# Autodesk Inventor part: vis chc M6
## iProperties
Library Location: C:\Program Files\Autodesk\Inventor 6\content
Library: local
SubLibrary: ISO
Family: 13
Member: 690
Member Major Revision: 1
Member Minor Revision: 1
Comments: To add or edit properties for Autodesk Inventor files, use iProperties.
Created: 2003-05
Part Number: vis chc M6
Vendor: Autodesk Inc.
Document SubType Name: Modeling
Designer: robert
Description: Vis cylindrique à six pans creux
Standard: ISO 4762 M6 x 60
Material: Steel, Mild
Alert: To add or edit properties for Autodesk Inventor files, use iProperties.
Control State: 0
Master: False
Checked Out: False
Shininess: 64.0
Length Units: 11269
Angle Units: 11279
Time Units: 11290
Mass Units: 11283
Length Display Precision: 3
Angle Display Precision: 2
Compacted: True
EGR: 1
Density: 0.0
Volumn: 0.0
Area: 0.0
PropertySet Name: Model Information
Author: robert
Revision Number: 1
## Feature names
1. Corps [Revolution]
2. Fente [Extrusion]
3. Congé1 [Fillet]
4. Chanfrein1 [Chamfer]
